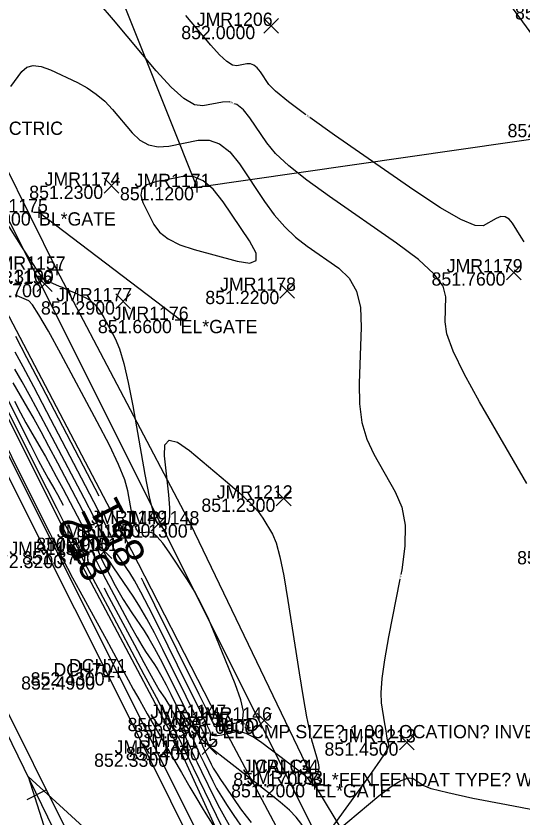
# Model space of a CAD drawing. Extents: x 1654928 to 1810050, y 486881 to 626330.
# Drawn here: x 1801380.2 to 1801426.1, y 489917.8 to 489990.4 of the extents above; entities that cross this region are included whole.
import ezdxf

# ---------------------------------------------------------------- set-up
doc = ezdxf.new("R2010")
doc.units = 0
for name, color, linetype in [('DR_X_Ditch', 7, 'Continuous'), ('DR_X_Storm_Sewer', 7, 'Continuous'), ('DT_X_Contour_Major', 7, 'Continuous'), ('DT_X_Contour_Minor', 7, 'Continuous'), ('PV_X_EOP', 7, 'Continuous'), ('PV_X_Shoulder', 7, 'Continuous'), ('RD_X_Fence', 7, 'Continuous'), ('RD_X_Gate', 7, 'Continuous'), ('RW_X_Esmt_SH', 7, 'Continuous'), ('SV_X_Break_Lines', 7, 'Continuous'), ('SV_X_Center_of_Pavt', 7, 'Continuous'), ('SV_X_CL_Survey_20', 7, 'Continuous'), ('SV_X_Random_Point', 7, 'Continuous'), ('SV_X_Shot_Marker', 7, 'Continuous'), ('SV_X_Text_Comment', 7, 'Continuous'), ('SV_X_Text_Elevation', 7, 'Continuous'), ('SV_X_Text_Name', 7, 'Continuous')]:
    doc.layers.add(name, color=color, linetype=linetype)

msp = doc.modelspace()

# ---------------------------------------------------------------- linework, layer by layer
at = {"layer": 'DR_X_Ditch'}
msp.add_lwpolyline([(1801398.424, 489926.897), (1801390.073, 489943.195), (1801378.941, 489964.397), (1801369.209, 489985.145), (1801358.751, 490002.608)], dxfattribs=at)
at = {"layer": 'DR_X_Storm_Sewer'}
msp.add_line((1801413.784, 489898.15), (1801398.867, 489926.256), dxfattribs=at)
at = {"layer": 'DT_X_Contour_Major'}
for points in [[(1801424.727, 489991.608), (1801426.019, 489989.843), (1801432.786, 489980.611)], [(1801400.385, 489926.52), (1801400.717, 489926.816), (1801400.766, 489927.488), (1801400.534, 489928.538), (1801400.02, 489929.965), (1801398.273, 489934.274), (1801397.622, 489935.805), (1801396.978, 489937.166), (1801396.342, 489938.357), (1801395.713, 489939.378), (1801394.046, 489941.875), (1801393.465, 489942.691), (1801392.973, 489943.267), (1801392.57, 489943.602), (1801392.255, 489943.696), (1801391.534, 489943.627), (1801391.279, 489943.708), (1801391.055, 489944.001), (1801390.863, 489944.507), (1801390.701, 489945.225), (1801390.313, 489947.425), (1801390.03, 489948.435), (1801389.474, 489949.815), (1801388.643, 489951.565), (1801387.539, 489953.685), (1801384.229, 489959.832), (1801383.117, 489961.86), (1801382.264, 489963.335), (1801381.668, 489964.256), (1801381.332, 489964.623), (1801380.298, 489965.071), (1801380.212, 489965.109), (1801380.146, 489965.179)], [(1801380.126, 489961.418), (1801381.139, 489959.492), (1801382.509, 489956.879), (1801386.637, 489948.991), (1801387.687, 489946.981)], [(1801377.822, 489958.907), (1801380.575, 489953.425), (1801381.506, 489951.579), (1801382.235, 489950.151), (1801382.763, 489949.142), (1801383.089, 489948.551), (1801383.69, 489947.533), (1801383.934, 489947.109), (1801384.215, 489946.602), (1801384.46, 489946.148)], [(1801391.519, 489939.556), (1801391.72, 489939.157), (1801392.725, 489937.136), (1801396.732, 489929.037), (1801397.449, 489927.584), (1801397.89, 489926.685), (1801398.055, 489926.339), (1801398.127, 489926.157), (1801398.21, 489926.111), (1801398.404, 489926.108), (1801398.709, 489926.149), (1801399.126, 489926.235), (1801400.385, 489926.52)], [(1801388.152, 489938.664), (1801388.387, 489938.218), (1801390.897, 489933.503), (1801391.744, 489931.922), (1801392.402, 489930.714), (1801392.871, 489929.88), (1801393.151, 489929.421), (1801393.645, 489928.693), (1801393.843, 489928.384), (1801394.064, 489928.001), (1801394.308, 489927.544), (1801394.577, 489927.014), (1801395.574, 489924.998), (1801395.76, 489924.617), (1801395.883, 489924.358), (1801395.944, 489924.224), (1801396.021, 489924.03), (1801396.101, 489923.852), (1801396.286, 489923.465), (1801396.574, 489922.869), (1801396.966, 489922.062), (1801398.151, 489919.632), (1801398.595, 489918.754), (1801399.041, 489917.942), (1801399.488, 489917.195)]]:
    msp.add_lwpolyline(points, dxfattribs=at)
at = {"layer": 'DT_X_Contour_Minor'}
for points in [[(1801399.57, 489982.585), (1801399.531, 489982.6), (1801398.876, 489982.59), (1801397.098, 489982.237), (1801396.333, 489982.337), (1801395.373, 489982.901), (1801394.217, 489983.929), (1801392.866, 489985.421), (1801389.003, 489990.018), (1801387.701, 489991.542)], [(1801406.422, 489981.445), (1801404.841, 489982.616), (1801403.654, 489983.581), (1801403.068, 489984.186), (1801402.307, 489985.318), (1801402.016, 489985.681), (1801401.713, 489985.922), (1801401.398, 489986.04), (1801401.07, 489986.035), (1801400.181, 489985.858), (1801399.783, 489985.927), (1801399.258, 489986.263), (1801398.603, 489986.868), (1801397.821, 489987.741), (1801395.563, 489990.428)], [(1801379.711, 489983.99), (1801380.717, 489985.346), (1801381.161, 489985.737), (1801381.74, 489985.894), (1801382.454, 489985.816), (1801383.302, 489985.504), (1801385.745, 489984.359), (1801386.629, 489983.884), (1801387.451, 489983.319), (1801388.21, 489982.662), (1801388.907, 489981.916), (1801390.683, 489979.803), (1801391.39, 489979.135), (1801392.181, 489978.714), (1801393.056, 489978.541), (1801394.015, 489978.616), (1801396.682, 489979.145), (1801397.664, 489979.16), (1801398.61, 489978.806), (1801399.52, 489978.084), (1801400.394, 489976.995), (1801402.675, 489973.598), (1801403.559, 489972.39), (1801404.497, 489971.314), (1801405.49, 489970.37), (1801406.538, 489969.558), (1801409.407, 489967.569), (1801410.34, 489966.677), (1801410.985, 489965.492), (1801411.344, 489964.013), (1801411.416, 489962.242), (1801411.226, 489957.129), (1801411.255, 489955.292), (1801411.486, 489953.617), (1801411.918, 489952.103), (1801412.551, 489950.749), (1801414.507, 489947.356), (1801415.094, 489945.959), (1801415.386, 489944.314), (1801415.384, 489942.419), (1801415.087, 489940.276), (1801415.007, 489939.866)], [(1801426.394, 489948.09), (1801422.136, 489955.475), (1801420.743, 489958.005), (1801419.757, 489960.055), (1801419.178, 489961.626), (1801419.006, 489962.718), (1801419.09, 489964.991), (1801418.834, 489965.933), (1801418.002, 489967.056), (1801416.595, 489968.36), (1801414.611, 489969.845), (1801408.555, 489974.044), (1801406.496, 489975.528), (1801404.863, 489976.831), (1801403.655, 489977.952), (1801402.872, 489978.892), (1801401.351, 489981.156), (1801400.768, 489981.883), (1801400.162, 489982.364), (1801399.963, 489982.438)], [(1801426.155, 489969.943), (1801425.903, 489970.372), (1801425.121, 489971.633), (1801424.808, 489972.015), (1801424.458, 489972.217), (1801424.07, 489972.237), (1801423.644, 489972.076), (1801422.458, 489971.407), (1801421.733, 489971.42), (1801420.446, 489971.962), (1801418.599, 489973.033), (1801416.19, 489974.634), (1801409.018, 489979.607), (1801406.761, 489981.198)], [(1801393.261, 489975.457), (1801392.798, 489975.365), (1801392.028, 489975.11), (1801391.584, 489974.716), (1801391.466, 489974.182), (1801391.675, 489973.509), (1801392.667, 489971.529), (1801393.174, 489970.83), (1801393.951, 489970.217), (1801394.997, 489969.69), (1801396.314, 489969.25), (1801400.185, 489968.192)], [(1801400.185, 489968.192), (1801401.343, 489968.01), (1801401.917, 489968.259), (1801401.905, 489968.938), (1801401.308, 489970.048), (1801398.935, 489973.58), (1801398.04, 489974.716), (1801397.133, 489975.475), (1801396.216, 489975.856), (1801395.288, 489975.859), (1801393.673, 489975.539)], [(1801378.351, 489973.142), (1801380.758, 489969.414), (1801381.556, 489968.187), (1801382.145, 489967.301), (1801382.527, 489966.758), (1801382.699, 489966.558), (1801382.881, 489966.478), (1801382.969, 489966.439), (1801383.099, 489966.383), (1801383.268, 489966.309), (1801383.479, 489966.218), (1801384.094, 489965.95), (1801384.349, 489965.84), (1801384.651, 489965.709), (1801385, 489965.557), (1801385.397, 489965.385), (1801386.519, 489964.899), (1801386.935, 489964.65), (1801387.342, 489964.267), (1801387.741, 489963.752), (1801388.13, 489963.103), (1801389.158, 489961.195), (1801389.546, 489960.279), (1801389.941, 489958.96), (1801390.342, 489957.239), (1801390.749, 489955.115), (1801391.844, 489948.916), (1801392.234, 489946.885), (1801392.583, 489945.441), (1801392.89, 489944.584), (1801393.157, 489944.314), (1801393.812, 489944.377), (1801394.009, 489944.562), (1801394.108, 489945.072), (1801394.11, 489945.906), (1801394.013, 489947.065), (1801393.624, 489950.586), (1801393.657, 489951.607), (1801394.047, 489952.027), (1801394.794, 489951.848), (1801395.899, 489951.069), (1801399.32, 489948.191), (1801400.483, 489947.18), (1801401.405, 489946.303), (1801402.087, 489945.56), (1801402.528, 489944.953), (1801403.383, 489943.512), (1801403.712, 489942.732), (1801404.057, 489941.474), (1801404.417, 489939.736), (1801404.793, 489937.519), (1801405.816, 489930.968), (1801406.173, 489928.747), (1801406.478, 489926.996), (1801406.73, 489925.714), (1801406.787, 489925.482)], [(1801376.832, 489959.84), (1801381.747, 489950.048), (1801382.972, 489947.611), (1801383.871, 489945.83), (1801384.444, 489944.703), (1801384.692, 489944.233), (1801384.917, 489943.851), (1801385.008, 489943.692), (1801385.114, 489943.502), (1801385.234, 489943.28), (1801385.743, 489942.31), (1801385.865, 489942.073), (1801385.95, 489941.9), (1801385.998, 489941.791), (1801386.009, 489941.746), (1801385.988, 489941.711), (1801386.136, 489941.408), (1801386.596, 489940.526), (1801387.369, 489939.065), (1801388.453, 489937.025), (1801391.759, 489930.812), (1801392.854, 489928.76), (1801393.656, 489927.264), (1801394.167, 489926.323), (1801394.386, 489925.938), (1801394.58, 489925.652), (1801394.658, 489925.53), (1801394.745, 489925.379), (1801394.842, 489925.199), (1801394.948, 489924.99), (1801395.414, 489924.045), (1801395.462, 489923.944), (1801395.486, 489923.891), (1801395.516, 489923.814), (1801395.6, 489923.637), (1801396.204, 489922.394), (1801396.723, 489921.327), (1801398.302, 489918.088), (1801398.85, 489916.981)], [(1801398.822, 489925.344), (1801398.429, 489925.273), (1801398.132, 489925.262), (1801397.933, 489925.31), (1801397.83, 489925.417), (1801397.686, 489925.781), (1801397.519, 489926.144), (1801397.125, 489926.957), (1801396.504, 489928.221), (1801395.657, 489929.936), (1801393.095, 489935.112), (1801392.211, 489936.874), (1801391.48, 489938.279), (1801390.902, 489939.327), (1801390.477, 489940.018), (1801389.548, 489941.384), (1801389.248, 489941.841), (1801389.046, 489942.187), (1801388.94, 489942.421), (1801388.931, 489942.544), (1801389.036, 489942.724), (1801388.906, 489943.096), (1801388.438, 489944.08), (1801387.632, 489945.673), (1801386.488, 489947.878), (1801382.986, 489954.57), (1801381.791, 489956.843), (1801380.833, 489958.644), (1801380.112, 489959.972)], [(1801397.696, 489924.267), (1801397.317, 489925.223), (1801397.147, 489925.602), (1801396.8, 489926.33), (1801396.276, 489927.405), (1801395.574, 489928.828), (1801393.466, 489933.087), (1801392.709, 489934.581), (1801392.019, 489935.867), (1801391.396, 489936.947), (1801390.84, 489937.819), (1801388.983, 489940.552), (1801388.64, 489941.064), (1801388.416, 489941.405), (1801388.311, 489941.575), (1801388.191, 489941.799), (1801388.16, 489941.885), (1801388.154, 489941.976), (1801388.174, 489942.071), (1801388.22, 489942.17), (1801388.378, 489942.439), (1801388.295, 489942.785), (1801387.928, 489943.622), (1801387.276, 489944.948), (1801386.339, 489946.764), (1801383.462, 489952.261), (1801382.442, 489954.194), (1801381.539, 489955.87), (1801380.754, 489957.288), (1801380.086, 489958.449)], [(1801379.884, 489957.187), (1801381.236, 489954.897), (1801381.785, 489953.944), (1801382.418, 489952.802), (1801383.136, 489951.472), (1801383.938, 489949.953), (1801386.19, 489945.651), (1801386.923, 489944.229), (1801387.433, 489943.191), (1801387.721, 489942.537), (1801387.786, 489942.266), (1801387.662, 489942.055), (1801387.665, 489941.905), (1801387.765, 489941.613), (1801387.962, 489941.18), (1801388.257, 489940.606), (1801389.173, 489938.884), (1801389.525, 489938.244), (1801389.894, 489937.614), (1801390.279, 489936.995), (1801390.681, 489936.386), (1801391.775, 489934.777), (1801392.211, 489934.092), (1801392.7, 489933.245), (1801393.242, 489932.235), (1801393.836, 489931.063), (1801395.491, 489927.72), (1801396.042, 489926.603), (1801396.454, 489925.759), (1801396.726, 489925.188), (1801396.859, 489924.89), (1801397.029, 489924.461), (1801397.103, 489924.282), (1801397.199, 489924.068), (1801397.315, 489923.818), (1801397.453, 489923.532), (1801397.847, 489922.722), (1801398.04, 489922.364), (1801398.323, 489921.899), (1801398.696, 489921.327), (1801399.158, 489920.647), (1801400.511, 489918.689), (1801401.003, 489918.01), (1801401.463, 489917.441)], [(1801380.04, 489955.547), (1801380.6, 489954.473), (1801381.082, 489953.58), (1801381.487, 489952.869), (1801382.463, 489951.215), (1801382.859, 489950.527), (1801383.317, 489949.702), (1801383.835, 489948.741), (1801384.415, 489947.644), (1801386.041, 489944.537), (1801386.57, 489943.51), (1801386.939, 489942.761), (1801387.147, 489942.288), (1801387.193, 489942.092), (1801387.104, 489941.94), (1801387.155, 489941.739), (1801387.375, 489941.251), (1801387.764, 489940.475), (1801388.322, 489939.412), (1801390.035, 489936.193), (1801390.635, 489935.083), (1801391.148, 489934.164), (1801391.575, 489933.438), (1801391.916, 489932.903), (1801392.71, 489931.735), (1801393.027, 489931.238), (1801393.382, 489930.623), (1801393.775, 489929.89), (1801394.207, 489929.039), (1801395.808, 489925.8), (1801396.107, 489925.188), (1801396.305, 489924.773), (1801396.402, 489924.557), (1801396.525, 489924.246), (1801396.602, 489924.067), (1801396.742, 489923.767), (1801396.945, 489923.343), (1801397.21, 489922.797), (1801397.999, 489921.177), (1801398.34, 489920.527), (1801398.772, 489919.791), (1801399.293, 489918.969), (1801399.905, 489918.062), (1801401.656, 489915.529)], [(1801377.74, 489954.618), (1801381.828, 489946.407), (1801383.235, 489943.594), (1801384.391, 489941.313), (1801385.295, 489939.565), (1801385.947, 489938.35), (1801387.862, 489934.892), (1801388.346, 489934.011), (1801388.801, 489933.177), (1801389.229, 489932.389), (1801390.332, 489930.349), (1801390.801, 489929.496), (1801391.38, 489928.468), (1801392.069, 489927.264), (1801392.868, 489925.886), (1801395.146, 489921.975), (1801395.926, 489920.641), (1801396.555, 489919.572), (1801397.035, 489918.768), (1801397.366, 489918.229), (1801398.557, 489916.33)], [(1801414.927, 489939.454), (1801413.905, 489934.228), (1801413.53, 489932.155), (1801413.295, 489930.471), (1801413.198, 489929.176), (1801413.239, 489928.271), (1801413.535, 489926.376), (1801413.637, 489925.74), (1801413.719, 489925.253), (1801413.782, 489924.914), (1801413.827, 489924.725), (1801413.919, 489924.418), (1801413.826, 489924.147), (1801413.478, 489923.565), (1801412.875, 489922.672), (1801412.017, 489921.468), (1801407.417, 489915.124), (1801405.965, 489917.384), (1801405.549, 489917.919), (1801404.924, 489918.554), (1801404.091, 489919.29), (1801403.048, 489920.127), (1801397.696, 489924.267)], [(1801406.888, 489925.074), (1801406.93, 489924.904), (1801407.391, 489923.368), (1801407.527, 489922.842), (1801407.587, 489922.415), (1801407.571, 489922.089), (1801407.48, 489921.862), (1801407.137, 489921.389), (1801407.02, 489921.241), (1801406.924, 489921.154), (1801406.851, 489921.127), (1801406.799, 489921.16), (1801406.691, 489921.329), (1801406.637, 489921.399), (1801406.555, 489921.481), (1801406.446, 489921.577), (1801406.31, 489921.687), (1801405.911, 489921.995), (1801405.692, 489922.164), (1801405.332, 489922.437), (1801404.833, 489922.817), (1801404.194, 489923.302), (1801402.303, 489924.736), (1801401.627, 489925.194), (1801401.018, 489925.492), (1801400.476, 489925.631), (1801400, 489925.611), (1801398.822, 489925.344)], [(1801386.998, 489916.394), (1801381.278, 489921.594), (1801384.501, 489911.447)], [(1801433.693, 489917.292), (1801424.558, 489919.025), (1801421.518, 489919.621), (1801419.249, 489920.112), (1801417.751, 489920.497), (1801417.024, 489920.776), (1801416.113, 489921.378), (1801415.663, 489921.45), (1801414.999, 489921.214), (1801414.12, 489920.67), (1801413.026, 489919.818), (1801407.417, 489915.124)]]:
    msp.add_lwpolyline(points, dxfattribs=at)
at = {"layer": 'PV_X_EOP'}
msp.add_lwpolyline([(1801533.684, 489642.188), (1801522.484, 489664.508), (1801511.881, 489685.341), (1801500.299, 489708.684), (1801491.104, 489726.659), (1801480.832, 489747.383), (1801466.882, 489774.659), (1801456.506, 489795.715), (1801444.637, 489819.009), (1801433.258, 489841.444), (1801422.029, 489863.995), (1801410.905, 489885.928), (1801399.817, 489908.089), (1801388.576, 489930.656), (1801376.228, 489955.188), (1801366.008, 489975.62), (1801354.725, 489997.894)], dxfattribs=at)
at = {"layer": 'PV_X_Shoulder'}
msp.add_lwpolyline([(1801534.471, 489642.456), (1801522.963, 489664.954), (1801512.6, 489685.485), (1801500.973, 489709.112), (1801491.766, 489727.019), (1801481.526, 489747.768), (1801467.484, 489775.07), (1801457.116, 489796.092), (1801445.57, 489819.398), (1801434.029, 489841.927), (1801422.682, 489864.343), (1801411.885, 489886.25), (1801400.664, 489908.455), (1801366.703, 489976.232), (1801355.676, 489998.276)], dxfattribs=at)
at = {"layer": 'RD_X_Fence'}
for points in [[(1801383.486, 490007.621), (1801396.544, 489974.905), (1801434.525, 489980.339), (1801464.866, 489979.647), (1801533.177, 489980.285)], [(1801406.8, 489921.921), (1801396.014, 489944.401), (1801383.891, 489967.432), (1801374.312, 489986.711), (1801364.337, 490006.337)]]:
    msp.add_lwpolyline(points, dxfattribs=at)
at = {"layer": 'RD_X_Gate'}
for p, q in [((1801382.265, 489972.623), (1801395.079, 489962.891)), ((1801415.218, 489907.69), (1801407.187, 489920.911))]:
    msp.add_line(p, q, dxfattribs=at)
at = {"layer": 'RW_X_Esmt_SH'}
msp.add_line((1801569.151, 489592.806), (1801345.762, 490039.449), dxfattribs=at)
at = {"layer": 'SV_X_Break_Lines'}
msp.add_lwpolyline([(1801445.791, 489822.136), (1801441.193, 489830.46), (1801435.211, 489842.68), (1801424.275, 489864.659), (1801412.811, 489886.984), (1801408.709, 489897.161), (1801400.001, 489913.183), (1801395.188, 489923.674), (1801385.653, 489941.642), (1801375.001, 489962.91), (1801364.942, 489983.144), (1801355.514, 490001.536)], dxfattribs=at)
at = {"layer": 'SV_X_Center_of_Pavt'}
msp.add_lwpolyline([(1801523.585, 489638.313), (1801512.853, 489659.481), (1801502.374, 489680.412), (1801490.819, 489703.952), (1801481.428, 489721.68), (1801470.803, 489742.834), (1801457.335, 489769.613), (1801446.389, 489792.464), (1801435.307, 489813.792), (1801423.54, 489836.522), (1801412.234, 489859.298), (1801401.202, 489881.345), (1801390.005, 489903.67), (1801378.784, 489926.715), (1801366.669, 489950.371), (1801356.567, 489970.63), (1801345.517, 489992.708)], dxfattribs=at)
at = {"layer": 'SV_X_CL_Survey_20'}
for p, q in [((1802886.975, 486913.246), (1801128.538, 490429.055)), ((1802886.975, 486913.246), (1801128.538, 490429.055)), ((1801382.944, 489920.396), (1801381.155, 489919.502))]:
    msp.add_line(p, q, dxfattribs=at)
at = {"layer": 'SV_X_Random_Point'}
for p, q in [((1801402.598, 489988.812), (1801403.931, 489990.147)), ((1801402.598, 489990.147), (1801403.931, 489988.812)), ((1801388.16, 489974.361), (1801389.493, 489975.696)), ((1801388.16, 489975.696), (1801389.493, 489974.361)), ((1801424.563, 489966.521), (1801425.896, 489967.856)), ((1801424.563, 489967.856), (1801425.896, 489966.521)), ((1801382.112, 489965.474), (1801383.446, 489966.809)), ((1801382.112, 489966.809), (1801383.446, 489965.474)), ((1801404.057, 489964.854), (1801405.39, 489966.189)), ((1801404.057, 489966.189), (1801405.39, 489964.854)), ((1801389.219, 489963.907), (1801390.552, 489965.242)), ((1801389.219, 489965.242), (1801390.552, 489963.907)), ((1801403.737, 489946.065), (1801405.07, 489947.4)), ((1801403.737, 489947.4), (1801405.07, 489946.065)), ((1801392.416, 489943.772), (1801393.75, 489945.107)), ((1801392.416, 489945.107), (1801393.75, 489943.772)), ((1801387.515, 489941.311), (1801388.848, 489942.646)), ((1801387.515, 489942.646), (1801388.848, 489941.311)), ((1801401.971, 489925.993), (1801403.304, 489927.328)), ((1801401.971, 489927.328), (1801403.304, 489925.993)), ((1801397.029, 489923.599), (1801398.363, 489924.934)), ((1801397.029, 489924.934), (1801398.363, 489923.599)), ((1801414.884, 489924.013), (1801416.218, 489925.347)), ((1801414.884, 489925.347), (1801416.218, 489924.013))]:
    msp.add_line(p, q, dxfattribs=at)
at = {"layer": 'SV_X_Shot_Marker'}
for p, q in [((1801396.044, 489974.905), (1801397.044, 489974.905)), ((1801396.544, 489975.405), (1801396.544, 489974.405)), ((1801396.544, 489974.905), (1801396.544, 489974.905)), ((1801381.765, 489972.623), (1801382.765, 489972.623)), ((1801382.265, 489973.123), (1801382.265, 489972.123)), ((1801382.265, 489972.623), (1801382.265, 489972.623)), ((1801383.391, 489967.432), (1801384.391, 489967.432)), ((1801383.891, 489967.932), (1801383.891, 489966.932)), ((1801383.891, 489967.432), (1801383.891, 489967.432)), ((1801395.079, 489963.391), (1801395.079, 489962.391)), ((1801394.579, 489962.891), (1801395.579, 489962.891)), ((1801395.079, 489962.891), (1801395.079, 489962.891)), ((1801395.514, 489944.401), (1801396.514, 489944.401)), ((1801396.014, 489944.901), (1801396.014, 489943.901)), ((1801396.014, 489944.401), (1801396.014, 489944.401)), ((1801390.073, 489943.695), (1801390.073, 489942.695)), ((1801389.573, 489943.195), (1801390.573, 489943.195)), ((1801390.073, 489943.195), (1801390.073, 489943.195)), ((1801385.653, 489942.142), (1801385.653, 489941.142)), ((1801385.153, 489941.642), (1801386.153, 489941.642)), ((1801385.653, 489941.642), (1801385.653, 489941.642)), ((1801389.433, 489931.523), (1801389.433, 489930.523)), ((1801388.076, 489930.656), (1801389.076, 489930.656)), ((1801388.576, 489931.156), (1801388.576, 489930.156)), ((1801388.576, 489930.656), (1801388.576, 489930.656)), ((1801388.933, 489931.023), (1801389.933, 489931.023)), ((1801389.433, 489931.023), (1801389.433, 489931.023)), ((1801397.924, 489926.897), (1801398.924, 489926.897)), ((1801398.424, 489927.397), (1801398.424, 489926.397)), ((1801398.424, 489926.897), (1801398.424, 489926.897)), ((1801398.367, 489926.256), (1801399.367, 489926.256)), ((1801398.867, 489926.756), (1801398.867, 489925.756)), ((1801398.867, 489926.256), (1801398.867, 489926.256)), ((1801395.188, 489924.174), (1801395.188, 489923.174)), ((1801394.688, 489923.674), (1801395.688, 489923.674)), ((1801395.188, 489923.674), (1801395.188, 489923.674)), ((1801406.3, 489921.921), (1801407.3, 489921.921)), ((1801406.3, 489921.921), (1801407.3, 489921.921)), ((1801406.8, 489922.421), (1801406.8, 489921.421)), ((1801406.8, 489922.421), (1801406.8, 489921.421)), ((1801406.8, 489921.921), (1801406.8, 489921.921)), ((1801406.8, 489921.921), (1801406.8, 489921.921)), ((1801407.187, 489921.411), (1801407.187, 489920.411)), ((1801406.687, 489920.911), (1801407.687, 489920.911)), ((1801407.187, 489920.911), (1801407.187, 489920.911))]:
    msp.add_line(p, q, dxfattribs=at)

# ---------------------------------------------------------------- texts
at = {"layer": 'DT_X_Contour_Major'}
for s, rotation, p in [('851', 117.3028, (1801392.068, 489941.524)), ('852', 116.2531, (1801389.059, 489940.195))]:
    msp.add_text(s, height=2.8, rotation=rotation, dxfattribs=at).set_placement(p)
at = {"layer": 'DT_X_Contour_Minor'}
for s, rotation, p in [('852', 339.50438, (1801399.593, 489982.502)), ('852', 323.98351, (1801406.421, 489981.357)), ('851', 11.22176, (1801393.35, 489975.403)), ('851', 258.93361, (1801414.924, 489939.804)), ('851', 283.81574, (1801406.738, 489925.39))]:
    msp.add_text(s, height=0.14, rotation=rotation, dxfattribs=at).set_placement(p)
at = {"layer": 'SV_X_Text_Comment'}
for s, p in [("BL*FEN FENDAT TYPE? WOOD HEIGHT? 4.5' OWNER? FARMER ELECTRIC", (1801327.157, 489979.625)), ('BL*GATE', (1801382.265, 489971.423)), ('EL*GATE', (1801395.079, 489961.691)), ('BL*D', (1801398.424, 489925.698)), ('EL*CMP SIZE? 1.00 LOCATION? INVERT CONDITION? DETERIORATED', (1801398.867, 489925.056)), ("BL*FEN FENDAT TYPE? WOOD HEIGHT? 4.5' OWNER? FARMER ELECTRIC", (1801406.8, 489920.72)), ('EL*GATE', (1801407.187, 489919.711))]:
    msp.add_text(s, height=1.2, dxfattribs=at).set_placement(p)
at = {"layer": 'SV_X_Text_Elevation'}
for s, p in [('852.3000', (1801425.34, 489990.06)), ('852.0000', (1801395.139, 489988.28)), ('852.0000', (1801424.661, 489979.411)), ('851.2300', (1801381.382, 489973.829)), ('851.1200', (1801389.592, 489973.705)), ('851.2900', (1801374.821, 489971.423)), ('851.3100', (1801376.9, 489966.232)), ('851.7600', (1801417.785, 489965.989)), ('851.1700', (1801375.826, 489964.942)), ('851.2200', (1801397.317, 489964.322)), ('851.2900', (1801382.441, 489963.375)), ('851.6600', (1801387.596, 489961.691)), ('851.2300', (1801396.959, 489945.533)), ('851.2500', (1801385.657, 489943.24)), ('851.1300', (1801389.023, 489943.201)), ('850.8900', (1801382.023, 489941.995)), ('852.3200', (1801377.754, 489940.442)), ('851.3700', (1801380.737, 489940.778)), ('851.6500', (1801425.527, 489940.786)), ('852.4900', (1801380.649, 489929.456)), ('852.4300', (1801381.506, 489929.823)), ('850.8000', (1801390.279, 489925.698)), ('850.6500', (1801390.817, 489925.056)), ('851.0900', (1801395.061, 489925.46)), ('851.4500', (1801408.097, 489923.48)), ('851.4000', (1801390.129, 489923.067)), ('852.3300', (1801387.252, 489922.474)), ('851.1700', (1801399.847, 489920.72)), ('851.1700', (1801399.847, 489920.72)), ('851.2000', (1801399.648, 489919.711))]:
    msp.add_text(s, height=1.2, dxfattribs=at).set_placement(p)
at = {"layer": 'SV_X_Text_Name'}
for s, p in [('JMR1206', (1801396.538, 489989.48)), ('JMR1174', (1801382.771, 489975.029)), ('JMR1171', (1801390.913, 489974.905)), ('JMR1175', (1801376.201, 489972.623)), ('JMR1157', (1801377.807, 489967.432)), ('JMR1179', (1801419.156, 489967.189)), ('JMR1156', (1801376.62, 489966.142)), ('JMR1178', (1801398.649, 489965.522)), ('JMR1177', (1801383.821, 489964.575)), ('JMR1176', (1801388.939, 489962.891)), ('JMR1212', (1801398.348, 489946.733)), ('JMR1149', (1801386.981, 489944.44)), ('JMR1148', (1801389.911, 489944.401)), ('JMR1150', (1801383.886, 489943.195)), ('JMR1152', (1801379.579, 489941.642)), ('JMR1151', (1801382.532, 489941.978)), ('DCH71', (1801384.963, 489931.023)), ('DCH70', (1801383.569, 489930.656)), ('JMR1147', (1801392.331, 489926.897)), ('JMR1146', (1801396.469, 489926.66)), ('JMR1137', (1801392.764, 489926.256)), ('JMR1145', (1801391.603, 489924.267)), ('JMR1213', (1801409.486, 489924.68)), ('JMR1144', (1801389.105, 489923.674)), ('JMR1134', (1801400.707, 489921.921)), ('CALC4', (1801401.811, 489921.921)), ('JMR1133', (1801401.085, 489920.911))]:
    msp.add_text(s, height=1.2, dxfattribs=at).set_placement(p)

doc.saveas('drawing.dxf')
